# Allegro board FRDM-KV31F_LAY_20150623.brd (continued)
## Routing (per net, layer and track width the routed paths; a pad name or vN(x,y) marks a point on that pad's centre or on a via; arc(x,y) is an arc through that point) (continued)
PTA4: length 41.6
  TOP w0.152: U13.38 53.1,25.34 53.1,25.34 v1(53.36,25.09) ; SW2.1 72.8,47.79 70.68,45.67 C56.1 68.11,45.07 68.11,44.65 R1.2 67.74,43.76 67.72,43.74 67.72,41.84 66.08,40.2 v1(58.84,40.2)
  INT_1 w0.152: v1(53.36,25.09) 56.91,25.09 58.84,27.02 v1(58.84,40.2)
PTA5: length 34.6
  TOP w0.152: v1(43.11,28.09) 43.58,28.09 43.95,28.47 49.27,28.47 51.29,26.45 51.29,26.45 U13.39
  INT_1 w0.152: v1(43.11,28.09) 42.39,28.82 42.39,44.39 40.35,46.43 40.35,49.67 J2.4
PTA12: length 30.5
  TOP w0.152: U13.42 50.23,25.39 50.23,25.39 49.5,26.11 v1(48.28,26.11)
  INT_1 w0.152: v1(48.28,26.11) 46.55,27.83 46.55,42.52 49.53,45.5 49.53,49.55 J1.12
PTA13: length 38.4
  TOP w0.152: v1(48.88,25.58) 49.33,25.58 49.88,25.04 49.88,25.03 U13.43
  INT_1 w0.152: J1.3 59.65,49.61 52.64,49.61 52.06,49.03 52.06,47.14 46.91,41.99 46.91,28.26 48.88,26.3 v1(48.88,25.58)
PTA17: length 45.4
  TOP w0.152: v1(41.56,26.07) 46.02,26.07 U13.47
  INT_1 w0.152: J2.15 23.96,48.29 27.47,44.78 39.25,44.78 41.05,42.97 41.05,26.58 v1(41.56,26.07)
PTB0: length 32.6
  TOP w0.152: U13.53 48.11,17.92 47.5,17.31 v1(45.4,17.31) ; C522.1 45.13,43.14 R555.1 43.6,43.13 43.6,42.73 43.61,42.72 v1(43.61,42.38)
  INT_1 w0.152: v1(43.61,42.38) 43.09,41.86 43.09,39.66 44.68,38.07 44.68,18.03 v1(45.4,17.31)
PTB0_RC: length 4.9
  TOP w0.152: J2.1 41.73,47.07 43.59,45.21 R555.2
PTB1: length 59.9
  TOP w0.152: U13.54 47.38,16.48 R48.2 44,17.21 30.74,17.21 v1(30.41,17.54)
  INT_1 w0.152: v1(30.41,17.54) 30.41,22.84 28.11,25.15 23.15,25.15 22.59,25.71 22.59,39.12 22.58,39.13 22.58,39.51 22.59,39.51 22.59,39.61 22.59,39.61 22.59,49.64 22.15,50.08 22.15,50.09 J2.18
PTB2: length 63.5
  TOP w0.152: v1(29.25,17.03) 29.65,16.62 40.53,16.62 42.2,14.95 44.17,14.95 R41.2 45.09,15.88 47.48,15.88 48.82,17.21 48.82,17.21 U13.55
  INT_1 w0.152: J2.20 18.87,50.82 20.17,49.52 20.17,45.22 21.81,43.57 21.81,25.2 22.59,24.43 27.65,24.43 29.25,22.83 v1(29.25,17.03)
PTB3: length 43.5
  TOP w0.152: v1(36.1,41.73) 36.06,41.78 C516.1 36.05,43.26 34.63,43.26 R549.1 ; v1(40.82,15.54) 41.73,14.63 46.94,14.63 U13.56
  INT_1 w0.152: v1(36.1,41.73) 38.62,41.73 40.25,40.1 40.25,34.19 39.96,33.9 39.96,32.65 40.46,32.16 40.46,15.9 v1(40.82,15.54)
PTB3_RC: length 4.2
  TOP w0.152: J2.7 34.11,47.01 34.61,46.51 R549.2
PTB10: length 62.6
  TOP w0.152: U13.58 48.02,14.3 41.24,14.3 39.44,16.09 29.15,16.09 v1(28.79,16.46)
  INT_1 w0.152: v1(28.79,16.46) 28.79,22.67 27.4,24.06 22.41,24.06 21.44,25.03 21.44,43.2 18.87,45.77 J2.19
PTB11: length 16.7
  TOP w0.152: U13.59 50.11,15.68 v1(50.11,15.24)
  INT_1 w0.152: v1(50.11,15.24) 50.11,10.15 54.65,5.61 54.65,3.85 J4.6
PTB18: length 28.6
  TOP w0.152: U13.64 52,14.03 52,14.02 48.73,10.76 32.21,10.76 31.17,9.72 v1(31.17,8.35) 31.17,7.51 30.45,6.78 30.45,6.16 30.44,6.16 J3.3
PTB19: length 32.9
  TOP w0.152: J3.1 29.04,3.98 31.12,3.98 31.76,4.62 v1(31.76,9.03) 31.76,9.58 32.6,10.42 49.08,10.42 52.34,13.68 52.35,13.68 U13.65
PTB20: length 67.9
  TOP w0.152: U13.66 49.47,10.08 40.01,10.08 39.8,9.87 v1(33.65,9.87)
  INT_1 w0.152: v1(33.65,9.87) 29.83,13.7 29.83,22.81 27.84,24.8 22.85,24.8 22.21,25.44 22.21,43.94 21.41,44.74 J2.17
PTB21: length 14.4
  TOP w0.152: U13.67 52.79,12.7 v1(52.79,12.25)
  INT_1 w0.152: v1(52.79,12.25) 56.08,8.96 59.59,8.96 61,7.55 J4.9
PTB22: length 26.6
  TOP w0.152: R64.2 56.43,35.5 v1(59.33,32.61) ; v1(55,22.3) 55,14.2 U13.68
  INT_1 w0.152: v1(55,22.3) 59.33,26.63 v1(59.33,32.61)
PTC0: length 14.6
  TOP w0.152: U13.70 53,10.79 53,10.79 v1(52.69,10.48)
  INT_1 w0.152: v1(52.69,10.48) 53.6,9.57 53.6,8.57 54.44,7.73 56.52,7.73 57.17,7.08 57.17,3.87 J4.8
PTC1: length 14.9
  TOP w0.152: U13.71 54.47,11.56 52.67,9.75 46.15,9.75 v1(45.69,9.29)
  INT_1 w0.152: v1(45.69,9.29) 45.69,5.13 J3.15
PTC2: length 18.9
  TOP w0.152: U13.72 53.04,9.41 47.18,9.41 v1(46.8,9.03)
  INT_1 w0.152: J3.13 44.36,3.9 46.22,3.9 46.8,4.48 v1(46.8,9.03)
PTC3: length 59.7
  TOP w0.152: v1(56.62,12.87) 56.62,12.29 U13.73 ; v1(62.11,45.6) 50.87,45.6 49.58,46.89 49.58,49.52 J1.14
  INT_1 w0.152: v1(56.62,12.87) 60.55,12.87 64.45,16.77 64.45,18.83 66,20.38 66,36.27 64.33,37.95 64.33,39.98 62.46,41.85 62.46,45.25 v1(62.11,45.6)
PTC4: length 26.5
  TOP w0.152: U13.76 59.82,10.14 59.82,9.26 58.48,7.93 38.97,7.93 v1(38.64,7.6)
  INT_1 w0.152: J3.9 38.06,7.02 38.32,7.28 38.32,7.28 v1(38.64,7.6)
PTC5: length 24.8
  TOP w0.152: v1(41.22,7.44) 41.68,7.44 41.82,7.58 58.76,7.58 60.33,9.15 60.33,10.34 U13.77
  INT_1 w0.152: v1(41.22,7.44) 40.6,6.82 J3.11
PTC6: length 62.6
  TOP w0.152: v1(61.07,10.58) 60.79,10.58 60.51,10.86 60.51,10.86 U13.78 ; v1(63.55,44.46) 63.23,44.78 61.55,44.78 61.39,44.94 49.04,44.94 47.04,46.94 47.04,49.51 J1.16
  INT_1 w0.152: v1(61.07,10.58) 61.74,10.58 64.94,13.78 64.94,18.47 66.54,20.07 66.54,26.07 67.33,26.86 67.33,29.03 67.99,29.68 67.99,35.48 65.25,38.22 65.25,40.17 63.55,41.87 63.55,43.71 63.55,44 63.55,44 v1(63.55,44.46)
PTC7: length 73.5
  TOP w0.152: U13.79 59.44,12.64 59.43,12.64 59.34,12.73 59.18,12.73 57.84,11.4 57.84,9.33 56.77,8.26 42.9,8.26 v1(42.1,9.07)
  INT_1 w0.152: v1(42.1,9.07) 42.1,26.64 41.44,27.3 41.44,43.57 39.58,45.43 29.35,45.43 27.23,47.54 27.23,47.55 J2.13
PTC8: length 20.7
  TOP w0.152: J4.2 52.2,3.94 52.2,5.81 52.93,6.54 61.93,6.54 62.64,7.25 62.64,10.15 61.23,11.56 61.23,11.56 U13.80
PTC9: length 19.3
  TOP w0.152: J4.4 54.62,3.82 61.85,3.82 62.25,4.22 62.25,6.26 63.19,7.2 63.19,10.3 U13.81
PTC10: length 17.9
  TOP w0.152: J4.12 64.82,3.86 64.82,5.85 65.36,6.39 66.88,6.39 R50.2 68.32,7.83 68.32,8.77 67.65,9.44 64.76,9.44 61.94,12.26 U13.82
PTC11: length 23.9
  TOP w0.152: J4.10 62.29,1.28 64,1.28 65.23,2.52 65.23,5.49 65.76,6.02 68.08,6.02 R49.2 68.68,7.81 68.68,8.96 67.83,9.81 65.1,9.81 U13.83
PTC12: length 48.7
  TOP w0.152: U13.84 64.98,10.64 v1(65.82,10.64)
  INT_1 w0.152: J1.1 67.2,44.6 67.2,42.83 68.49,41.54 68.49,39.85 71.44,36.9 71.44,21.79 67.77,18.13 67.77,12.14 66.27,10.64 v1(65.82,10.64)
PTC13: length 59.7
  TOP w0.152: v1(65.44,11.29) 65.03,11.29 U13.85 ; v1(64.39,46.68) 64.07,47 60.27,47 59.92,46.66 55.1,46.66 54.6,47.15 54.6,49.57 J1.10
  INT_1 w0.152: v1(64.39,46.68) 66.79,44.27 66.79,42.67 68.1,41.36 68.1,39.65 71.04,36.71 71.04,21.96 67.27,18.19 67.27,12.3 66.27,11.29 v1(65.44,11.29)
PTC15: length 50.2
  TOP w0.152: v1(65.11,11.93) 63.97,13.06 63.97,13.75 63.69,14.04 63.69,14.04 U13.87
  INT_1 w0.152: v1(65.11,11.93) 66.19,11.93 66.87,12.61 66.87,18.35 70.64,22.12 70.64,36.51 67.72,39.43 67.72,41.13 66.44,42.4 66.44,43.91 63.14,47.21 59.5,47.21 58.43,48.28 J1.5
PTC16: length 47.3
  TOP w0.152: v1(66.28,14.55) 65.3,14.55 64.75,15.1 64.75,15.1 U13.90
  INT_1 w0.152: v1(66.28,14.55) 66.28,18.33 70.22,22.27 70.22,36.36 67.34,39.24 67.34,40.94 66.06,42.22 66.06,43.66 63.02,46.7 58.52,46.7 58.51,46.71 57.11,48.11 57.11,48.11 56.93,48.29 J1.7
PTC17: length 49.3
  TOP w0.152: v1(65.79,15.22) 65.35,15.22 65.11,15.46 65.11,15.46 U13.91 ; v1(65.57,43.31) 65.57,44.67 63.71,46.52 60.38,46.52 60.18,46.33 54.07,46.33 53.35,47.05 J1.9
  INT_1 w0.152: v1(65.79,15.22) 65.79,15.66 65.79,15.67 65.79,18.44 69.8,22.46 69.8,36.16 66.98,38.98 66.98,40.65 65.57,42.06 v1(65.57,43.31)
PTC18: length 27.9
  TOP w0.152: v1(47.64,32.01) 47.64,32.81 47.78,32.95 47.78,34.76 U8.9 ; v1(54.01,23.67) 57.61,23.67 U13.92
  INT_1 w0.152: v1(54.01,23.67) 53.3,23.67 47.64,29.33 v1(47.64,32.01)
PTD0: length 27.3
  TOP w0.152: v1(48.89,31.9) 48.89,32.36 48.78,32.47 U8.11 ; v1(54.5,24.14) 57.85,24.14 64.39,17.61 64.39,17.59 U13.93
  INT_1 w0.152: v1(48.89,31.9) 48.89,28.65 53.4,24.14 v1(54.5,24.14)
PTD1: length 9.3
  TOP w0.152: R69.1 73.12,13.37 v1(71.44,13.37) 69.32,13.37 66.19,16.51 66.18,16.51 U13.94
PTD2: length 55.8
  TOP w0.152: v1(74.86,30.88) 74.4,30.88 74.39,30.89 74.33,30.89 73.56,31.66 71.24,31.66 69.25,33.65 66.79,33.65 63.65,36.78 56.7,36.78 55.9,37.58 55.9,39.61 55.68,39.83 55.68,41.54 R9.2 54.31,42.92 48.82,42.92 48.26,42.36 v1(48.26,40.92) 48.26,37.33 U8.4 ; v1(72.03,17.5) 72.03,17.04 72.02,17.03 72.02,16.09 R56.2
  INT_1 w0.152: v1(74.86,30.88) 74.86,22.79 72.02,19.95 72.02,17.96 72.03,17.96 v1(72.03,17.5)
PTD3: length 61.5
  TOP w0.152: v1(74.38,31.59) 73.92,32.05 71.37,32.05 69.42,34.01 66.95,34.01 63.84,37.12 57.44,37.12 56.83,37.73 56.83,41.45 R15.2 56.2,42.09 55.01,43.28 48.49,43.28 46.39,41.19 46.39,39.87 43.91,37.39 v1(43.91,36.9) 44.29,36.52 47.49,36.52 U8.6 ; v1(71.17,17.86) 71.17,17.43 R57.1
  INT_1 w0.152: v1(71.17,17.86) 71.17,19.67 74.38,22.89 v1(74.38,31.59)
PTD4: length 44.1
  TOP w0.152: U13.97 68.13,16.68 v1(68.98,16.68) ; J3.7 36.73,6.32 41.84,6.32 42.41,6.9 61.15,6.9 v1(61.79,7.53)
  INT_1 w0.152: v1(68.98,16.68) 68.98,12.1 66.47,9.6 63.85,9.6 v1(61.79,7.53)
PTD5: length 45.5
  TOP w0.152: U13.98 66.87,18.65 67.6,17.92 67.6,17.92 68.04,17.47 68.05,17.47 v1(68.37,17.15) ; v1(61.48,8.29) 60.43,7.25 42.06,7.25 41.55,6.75 34.61,6.75 J3.5
  INT_1 w0.152: v1(61.48,8.29) 63.23,10.05 66.3,10.05 68.37,12.12 v1(68.37,17.15)
PTD6: length 61.4
  TOP w0.152: U13.99 66.5,19.73 63.08,19.73 59.57,23.24 59.57,23.24 v1(59.25,23.56)
  INT_1 w0.152: J2.6 36.65,50.86 38.09,52.3 42.33,52.3 44.23,50.4 44.23,42.25 43.45,41.47 43.45,39.86 45.03,38.29 45.03,26.73 51.03,20.73 56.42,20.73 v1(59.25,23.56)
PTD7: length 9.3
  TOP w0.152: R74.2 73.17,17.28 72.06,18.39 68.53,18.39 68.29,18.63 68.29,18.64 U13.100
PTE0: length 36.4
  TOP w0.152: v1(72.41,24.58) 71.76,23.94 R58.2
  INT_1 w0.152: v1(72.41,24.58) 72.41,32.4 72.41,32.4 72.41,33.06 72.41,33.06 72.41,37.1 69.16,40.35 69.16,42.07 68.16,43.07 68.16,44.92 65.02,48.06 65.02,51.16 64.13,52.05 62.22,52.05 61.72,51.55 61.7,51.55 J1.4
PTE1: length 30
  TOP w0.152: R59.1 71.35,25.38 71.35,25.37 71.62,25.37 v1(71.95,25.7)
  INT_1 w0.152: v1(71.95,25.7) 71.95,26.15 71.94,26.16 71.94,36.99 68.83,40.11 68.83,41.78 67.64,42.96 67.64,44.85 67.26,45.23 67.26,45.23 66.9,45.58 66.9,45.59 64.7,47.79 64.7,49.65 64.25,50.1 64.24,50.1 J1.2
PTE2: length 41.8
  TOP w0.152: v1(65.05,43.83) 65.05,44.29 65.05,44.63 63.54,46.14 60.62,46.14 60.44,45.97 51.7,45.97 50.81,46.86 J1.11 ; 66.87,22.54 68.08,23.75 68.29,23.75 v1(68.73,24.19)
  INT_1 w0.152: v1(68.73,24.19) 69.37,24.83 69.37,35.99 66.57,38.79 66.57,40.47 65.05,41.99 65.05,43.38 v1(65.05,43.83)
PTE3: length 43
  TOP w0.152: v1(64.57,43.35) 64.57,44.34 63.79,45.12 61.67,45.12 61.53,45.26 49.95,45.26 48.27,46.94 J1.13 ; U13.4 67.23,23.6 v1(67.99,24.37)
  INT_1 w0.152: v1(67.99,24.37) 68.92,25.29 68.92,35.79 66.14,38.56 66.14,40.34 64.57,41.92 v1(64.57,43.35)
PTE4: length 29.1
  TOP w0.152: v1(72.19,8.79) 72.19,8.33 72.28,8.24 C55.1 R75.2 72.28,5.31 72.8,4.79 SW3.1 ; R67.2 69.97,25.65 70.82,26.49 72.55,26.49 73.35,25.69 v1(73.35,24.64)
  INT_1 w0.152: v1(72.19,8.79) 72.19,9.32 70.51,11 70.51,19.65 73.35,22.49 v1(73.35,24.64)
PTE5: length 39.2
  TOP w0.152: v1(72.9,27.14) 72.43,27.14 72.43,27.14 69.1,27.14
  INT_1 w0.152: v1(72.9,27.14) 72.9,27.63 72.89,27.63 72.89,28.66 72.89,28.66 72.89,37.21 69.53,40.57 69.53,42.35 68.66,43.22 68.66,44.97 65.41,48.23 65.41,49.43 65.41,49.44 65.41,50.08 65.41,50.09 65.41,51.4 64.36,52.44 60.05,52.44 J1.6
PTE6: length 36.3
  TOP w0.152: U13.7 66.18,24.68 67.05,25.54 67.07,25.54 v1(67.39,25.86) ; v1(56.93,47.15) 56.93,47.61 57.15,47.83 57.15,49.57 J1.8
  INT_1 w0.152: v1(56.93,47.15) 57.92,46.17 62.78,46.17 64.08,44.87 64.08,41.88 65.74,40.22 65.74,38.34 68.43,35.65 68.43,29.58 67.82,28.98 67.82,26.29 v1(67.39,25.86)
PTE16: length 42
  TOP w0.152: J1.15 45.73,46.94 48.06,44.6 61.14,44.6 61.3,44.44 62.61,44.44 v1(63,44.06) ; v1(66.61,27.23) 66.29,26.91 U13.10
  INT_1 w0.152: v1(63,44.06) 63,43.6 63,43.6 63,41.87 64.8,40.06 64.8,38.06 67.52,35.34 67.52,29.79 66.94,29.21 66.94,27.56 v1(66.61,27.23)
PTE17: length 60.2
  TOP w0.152: U13.11 62.19,23.51 61.39,23.51 60.54,24.36 v1(60.06,24.36) ; J2.12 30.36,49.5 30.36,43.44 32.04,41.76 34.02,41.76 35.86,39.92 v1(44.19,39.92)
  INT_1 w0.152: v1(44.19,39.92) 45.42,38.68 45.42,26.95 51.29,21.09 55.9,21.09 59.17,24.36 v1(60.06,24.36)
PTE18: length 54.1
  TOP w0.152: v1(59.56,24.87) 60.76,24.87 61.38,24.25 62.21,24.25 62.96,24.99 62.96,24.99 U13.12 ; v1(43.93,40.92) 38.56,40.92 37.08,42.4 37.08,45.87 35.36,47.6 35.36,49.58 J2.8
  INT_1 w0.152: v1(59.56,24.87) 59.06,24.87 55.65,21.46 51.56,21.46 45.8,27.22 45.8,39.05 44.25,40.59 44.25,40.6 v1(43.93,40.92)
PTE19: length 56.3
  TOP w0.152: v1(58.95,25.38) 60.89,25.38 61.56,24.71 61.97,24.71 U13.13 ; v1(45.21,40.39) 36.52,40.39 33.94,42.97 33.94,46.39 32.88,47.45 32.88,49.51 J2.10
  INT_1 w0.152: v1(45.21,40.39) 46.17,39.44 46.17,27.5 51.83,21.84 55.41,21.84 v1(58.95,25.38)
PTE24: length 34.2
  TOP w0.152: U13.31 53.31,30.08 53.25,30.08 53.25,30.09 43.39,30.09 v1(43.13,30.34)
  INT_1 w0.152: v1(43.13,30.34) 42.75,30.72 42.75,42.34 43.62,43.21 43.62,48.94 J2.2
PTE25: length 45
  TOP w0.152: U13.32 54.51,28.19 v1(55.52,27.19) ; v1(75.37,30.24) 74.28,30.24 73.27,31.25 71.11,31.25 69.08,33.29 66.57,33.29 63.41,36.45 58.41,36.45 v1(57.74,35.78) ; R73.2 73.34,18.35 73.07,18.35 v1(72.58,18.84)
  INT_1 w0.152: v1(57.74,35.78) 57.29,35.32 57.29,28.96 v1(55.52,27.19) ; v1(75.37,30.24) 75.37,22.78 72.58,19.98 v1(72.58,18.84)
RST_TGTMCU_B: length 149.7
  TOP w0.152: v1(24.92,39.74) 25.2,39.46 R10.2 R11.2 U3.7 ; TP33.1 67.92,40.45 67.06,39.58 58.04,39.58 57.41,40.21 57.41,42.51 56.32,43.6 48.27,43.6 45.94,41.27 45.94,40.11 45.12,39.29 35.9,39.29 33.81,41.38 31.85,41.38 29.38,43.85 25.25,43.85 v1(24.92,43.53) 24.42,43.53 24.35,43.46 11.84,43.46 10.25,41.87 D1.C 6.76,42.44 6.75,42.45 6.75,42.64 6.5,42.89 4.82,42.89 4.42,43.29 J25.3 ; v1(30.95,18.24) 31.37,17.81 38.64,17.81 38.64,17.82 v1(39.25,17.82) 47.3,17.82 47.76,18.27 U13.52
  TOP w0.203: J9.10 73.15,38.1 70.8,40.45 70.22,40.45 70.22,40.45 TP33.1
  INT_1 w0.152: J3.6 34.26,3.86 34.26,10.62 30.95,13.93 v1(30.95,18.24) 30.95,22.9 28.34,25.5 27.09,25.5 26.49,26.1 26.49,37.49 24.92,39.06 v1(24.92,39.74) 24.92,43.08 24.92,43.08 v1(24.92,43.53)
SDA_EXTAL: length 6.3
  TOP w0.152: U5.17 16.88,38.73 17.36,38.73 17.55,38.55 17.55,37.13 C9.1 18.76,36.43 19.07,36.74 Y1.3
SDA_JTAG_TCLK: length 11.7
  TOP w0.152: J10.4 13.91,30.14 TP26.1 ; v1(16.29,34.67) 15.98,34.98 15.98,34.99 15.87,35.09 15.01,35.95
  INT_1 w0.152: v1(16.29,34.67) 16.29,31.39 13.91,29.02 J10.4
SDA_JTAG_TDI: length 12
  TOP w0.152: J10.8 16.45,29.38 16.7,29.63 TP28.1 ; U5.13 17.14,34.53 17.14,34.53 v1(17.45,34.22)
  INT_1 w0.152: J10.8 16.45,29.8 17.45,30.8 v1(17.45,34.22)
SDA_JTAG_TDO: length 12.2
  TOP w0.152: TP27.1 15.33,29.59 15.18,29.43 J10.6 ; U5.14 16.63,35.75 16.63,35.74 v1(16.94,35.43)
  INT_1 w0.152: J10.6 15.18,29.58 16.94,31.34 v1(16.94,35.43)
SDA_JTAG_TMS: length 14.2
  TOP w0.152: U5.15 16.07,36.99 v1(16.72,36.35) R21.2 18.25,33.85 TP25.1
  INT_1 w0.152: J10.2 13.13,28.45 13.13,28.92 15.78,31.57 15.78,35.42 v1(16.72,36.35)
SDA_LED: length 9.8
  TOP w0.152: U5.29 10.69,40.28 3.3,40.28 2.98,39.95 D2.C
SDA_LED_R: length 5.7
  TOP w0.152: v1(1.99,37.77) 2.96,37.77 D2.A ; R17.2 2.93,34.31 2.18,34.31 1.91,34.58 v1(1.88,34.58)
  INT_1 w0.152: v1(1.99,37.77) 1.56,37.34 1.56,34.9 v1(1.88,34.58)
SDA_RST: length 20.7
  TOP w0.152: J10.10 17.72,28.77 TP29.1 ; U5.19 16.48,39.75 16.54,39.75 v1(16.85,40.06) ; TP5.1 18.77,32.38 v1(18.77,32.97) 19.21,32.97 19.24,32.94 R6.1 R5.2
  INT_1 w0.152: v1(16.85,40.06) 17.66,39.25 17.66,39.25 17.66,35.67 18.77,34.56 v1(18.77,32.97) 18.3,32.5 18.3,30.77 17.72,30.19 J10.10
SDA_RST_LED: length 1.4
  TOP w0.152: D1.A 4.6,41.87 4.59,41.85 R2.2
SDA_RST_TGTMCU_B: length 6.2
  TOP w0.152: 15.01,39.7 15.41,40.1 15.41,40.1 15.53,40.21 15.53,40.21 v1(15.85,40.54)
  INT_1 w0.152: v1(15.85,40.54) 15.85,41.38 13.58,43.65 13.58,44.6 J5.2
SDA_RST_TGTMCU_J_B: length 34
  TOP w0.152: v1(24,43.94) 22.46,43.94 21.83,44.57 21.83,44.57 21.78,44.62 J5.1 16.14,45.59 15.89,45.84 10.71,45.84 J25.1 ; U3.2 29.37,38.56 29.51,38.42 29.51,37.23 R14.2 28.23,35.96 v1(25.83,35.96) 25.37,35.96 25.37,35.96 25.21,35.96 24.94,36.23 24.94,37.68 R10.1
  INT_1 w0.152: v1(25.83,35.96) 25.83,37.46 24.32,38.97 24.32,43.62 v1(24,43.94)
SDA_RX_EN: length 3.4
  TOP w0.152: U7.5 34.16,36.04 34.18,36.06 R16.1 34.7,35.64 34.84,35.5 v1(34.84,35.04) 34.84,34.93 34.81,34.9 34.81,34.87 R23.2
SDA_SPI0_CS: length 12.2
  TOP w0.152: R3.2 24.08,40.81 TP1.1 23.53,41.36 15.26,41.36 14.7,40.8 U5.23
SDA_SPI0_RST_B: length 17.7
  TOP w0.152: U5.22 15.05,40.45 15.63,41.02 22.87,41.02 v1(23.12,40.77) ; TP6.1 23.6,36.65 23.59,36.64 23.59,36.34 23.74,36.19 23.74,36.15 v1(23.75,36.14) 24.2,36.14 24.22,36.13 24.3,36.13 25.01,35.43 R18.2
  INT_1 w0.152: v1(23.12,40.77) 23.63,40.26 23.63,36.72 23.75,36.6 v1(23.75,36.14)
SDA_SPI0_SCK: length 24.3
  TOP w0.152: U2.3 33.64,40.61 33.36,40.89 31.77,40.89 30.28,42.37 12.69,42.37 12.28,41.97 12.28,40.8 U5.26
SDA_SPI0_SIN: length 34.6
  TOP w0.152: v1(27.16,43.2) 26.47,43.2 26.34,43.06 12.17,43.06 11.43,42.32 11.43,40.24 U5.28 ; U10.5 30.09,29.08 29.5,29.67 29.11,29.67 v1(28.8,29.98)
  INT_1 w0.152: v1(27.16,43.2) 27.92,42.44 27.92,38.71 28.8,37.83 v1(28.8,29.98)
SDA_SPI0_SOUT: length 31.1
  TOP w0.152: U12.3 30.08,32.4 30.08,32.41 v1(30.08,32.86) ; U5.27 11.8,40.58 11.8,42.11 12.41,42.72 27.65,42.72 27.83,42.9 v1(28.3,42.9)
  INT_1 w0.152: v1(30.08,32.86) 30.08,33.32 30.07,33.33 30.07,33.47 30.07,33.47 30.07,34.88 29.84,35.11 29.84,41.34 29.82,41.36 29.82,41.38 28.62,42.58 28.62,42.58 v1(28.3,42.9)
SDA_SWD_EN: length 2.5
  TOP w0.152: U9.6 27.49,35.42 R18.1 R19.1
SDA_SWD_EN_B: length 10.3
  TOP w0.152: R25.2 24.76,34.81 24.76,35.06 24.23,35.6 23.61,35.6 23.46,35.44 TP52.1 18.14,35.44 17.24,36.34 17.24,36.56 U5.16
SDA_SWD_EN_B_R: length 2.4
  TOP w0.152: U9.1 27.14,33.38 27.11,33.4 R26.2 25.16,33.4 R25.1
SDA_SWD_EN_R: length 6.7
  TOP w0.152: R19.2 30.42,35.43 31.35,36.36 R13.1 31.35,37.9 31.37,37.91 R12.2 31.37,39.24 31.89,39.76 U2.5
SDA_SWD_OE: length 16.5
  TOP w0.152: v1(24.66,32.11) 24.88,31.88 28.45,31.88 29.16,32.6 29.16,33.54 28.75,33.95 28.67,33.95 U9.4 28.49,34.31 28.76,34.58 31.21,34.58 R33.1 ; R3.1 24.08,37.43 v1(24.48,37.02)
  INT_1 w0.152: v1(24.66,32.11) 24.48,32.28 v1(24.48,37.02)
SDA_SWD_OE_B: length 14.5
  TOP w0.152: v1(23.17,39.32) 23.17,39.86 22.81,40.22 TP50.1 22.11,40.61 16.63,40.61 15.75,39.73 U5.20 ; R28.2 24.15,34.74 v1(23.83,35.07)
  INT_1 w0.152: v1(23.17,39.32) 23.17,35.72 v1(23.83,35.07)
SDA_SWD_OE_B_R: length 6.9
  TOP w0.152: R27.1 23.64,33.35 23.65,33.36 R28.1 24.95,32.56 v1(25.64,32.56) 26.02,32.18 28.26,32.18 28.49,32.42 U9.3
SDA_SWD_OE_R: length 7.1
  TOP w0.152: R39.1 32.42,30.79 31.91,30.28 30.8,30.28 30.58,30.5 U12.5 ; R39.1 32.94,31.31 31.68,32.57 R33.2 ; R39.1 32.94,29.63 R37.2
SDA_USB_CONN_DN: length 17
  TOP w0.152: R22.1 9.51,34.31 8.86,33.66 8.86,33.39 v1(9.12,33.14) ; J6.2 5.09,26.52 5.27,26.34 6.77,26.34 U4.1 8.07,26.37 10.1,26.37 v1(10.31,26.59)
  INT_1 w0.152: v1(10.31,26.59) 9.99,26.27 9.6,26.27 8.85,27.02 8.85,32.88 v1(9.12,33.14)
SDA_USB_CONN_DP: length 17.9
  TOP w0.152: R20.1 9.25,34.57 8.55,33.86 8.55,33.43 v1(8.26,33.14) ; J6.3 4.16,25.87 5.15,25.87 5.31,26.03 6.83,26.03 7.45,25.41 U6.1 8.15,26.06 9.98,26.06 v1(10.31,25.73)
  INT_1 w0.152: v1(10.31,25.73) 10.11,25.94 9.47,25.94 8.52,26.88 8.52,27.15 8.52,32.88 v1(8.26,33.14)
SDA_USB_DN: length 1.7
  TOP w0.152: U5.4 11.47,36.15 11.35,36.15 10.68,35.49 R22.2
SDA_USB_DP: length 1.8
  TOP w0.152: U5.3 11.11,36.51 11.11,36.36 10.48,35.73 R20.2
SDA_USB_P5V_SENSE: length 6
  TOP w0.152: R8.2 R7.1 7.4,39.36 7.4,39.36 v1(7.78,39.74) 7.78,39.74 10.52,39.74 U5.30
SDA_USBSHIELD: length 20.9
  TOP w0.152: J6.S1 5.37,28.1 ; 2.62,30.05 J6.S3 1.48,31.55
  TOP w0.381: 3.87,30.85 L1.1 5.33,28.96 4.48,28.11 J6.S1 4.31,28.1 3.68,28.73
  BOTTOM w0.127: J6.S2 4.48,24.37 ; J6.S2 3.59,23.65 ; J6.S2 4.48,22.92 ; J6.S2 5.37,23.65 ; J6.S3 2.62,30.05 ; J6.S3 1.48,29.31 ; J6.S3 1.48,30.78 ; 3.59,28.1 J6.S1 ; J6.S1 4.48,28.82 ; J6.S1 4.48,27.37 ; J6.S1 5.37,28.1 ; 1.48,20.96 J6.S4 ; J6.S4 1.48,22.43 ; J6.S4 2.62,21.7
SDA_VOUT33: length 12.3
  TOP w0.203: v1(11.38,35.34) 11.56,35.52 11.56,35.54 U5.5
  TOP w0.508: C11.1 6.99,34.36 v2(5.84,34.36) 4.72,34.36 R36.2 4.52,34.28 3.93,33.7 3.92,33.7 TP15.1
  INT_1 w0.381: v2(5.84,34.36) 5.84,35.05 6.69,35.9 9.55,35.9 10.1,35.35 11.36,35.35 v1(11.38,35.34)
SDA_XTAL: length 5
  TOP w0.152: 16.07,38.64 16.47,39.03 16.48,39.03 16.88,39.44 C6.1 18.88,39.44 19.18,39.14 19.36,39.14 19.37,39.13 Y1.1
SW1_RST_B: length 6.5
  TOP w0.152: v1(7.4,47.38) 7.42,47.38 7.43,47.39 C2.1 8.28,48.38 8.02,48.64 SW1.2
  INT_1 w0.152: v1(7.4,47.38) 6.96,46.94 J25.2
SWD_CLK_KV3X: length 21.1
  TOP w0.152: J11.1 36.72,34.9 36.72,33.28 36.96,33.04 39.38,33.04 42.71,29.7 50.81,29.7 52.3,28.21 53.06,28.21 U13.34
SWD_CLK_TGTMCU: length 47.1
  TOP w0.152: TP31.1 70.16,36.61 66.03,36.61 64.31,38.34 v1(57.38,38.34) ; J8.2 39.37,31.02 40.89,31.02 41.75,30.16 41.75,29.55 TP42.1 42.06,29.24 v1(50.63,29.24)
  TOP w0.203: J9.4 73.73,34.29 71.4,36.62 TP31.1
  INT_1 w0.152: 39.26,34.87 39.25,34.86 J11.2 39.32,34.84 39.32,31.08 J8.2 ; v1(50.63,29.24) 56.13,34.74 56.13,37.09 v1(57.38,38.34)
SWD_CLK_TGTMCU_BUF: length 12.1
  TOP w0.152: U2.4 v1(31.99,40.26)
  INT_1 w0.152: J8.1 36.78,31.08 36.78,32.39 33.63,35.53 33.63,35.53 33.46,35.7 33.46,38.78 v1(31.99,40.26)
SWD_DIO_TGTMCU: length 46
  TOP w0.152: v1(57.73,37.65) 63.97,37.65 66.06,35.56 TP30.1 ; J12.2 40.33,27.48 40.43,27.58 TP41.1 43,28.84 50.31,28.84 50.71,28.44 50.72,28.44 v1(51.04,28.12) 52,27.16 52,27.15 U13.37
  TOP w0.203: TP30.1 73.77,33.02 J9.2
  INT_1 w0.152: v1(57.73,37.65) 56.71,36.63 56.71,33.79 v1(51.04,28.12)
SWD_DIO_TGTMCU_BUF: length 15.3
  TOP w0.152: U12.4 30.08,30.45 30.53,30.01 32.2,30.01 32.4,29.8 32.4,29.41 32.74,29.07 35.24,29.07 J12.1 35.92,26.57 33.97,26.57 31.97,28.58 U10.2
TC_EXTAL_TP: length 4
  TOP w0.152: TP9.1 16.15,33.4 14.7,34.85 14.7,34.85 U5.10
TC_SDA_USB_ID_TP: length 4.3
  TOP w0.203: J6.4 4.16,25.22 5.28,25.22 TP7.1
TC_XTAL_TP: length 2.3
  TOP w0.152: TP10.1 14.86,33.98 14.33,34.5 14.33,34.51 U5.9
THER_A: length 13.4
  TOP w0.152: R47.2 68.91,28.96 71.28,28.96 C21.1 72.17,28.59 72.5,28.92 73.33,28.92 74.27,27.98 77.28,27.98 77.51,27.75 77.51,27.53 76.95,26.97 RT1.1 76.95,25.19 R45.2
THER_B: length 12.9
  TOP w0.152: R44.1 78.48,25.17 RT1.2 78.48,26.97 77.84,27.61 77.84,27.92 77.51,28.26 74.47,28.26 73.53,29.2 72.05,29.2 C21.2 71.28,29.24 69.76,29.24 R46.2
TP_2102_A: length 2.1
  TOP w0.152: U3.3 29.27,38.96 30.06,39.74 30.06,39.79 30.07,39.8 TP3.1
TP_2102_B: length 2.4
  TOP w0.152: U3.6 26.76,39.36 TP2.1
TRACE_SWO: length 4.4
  TOP w0.203: R80.1 72.65,37.89 72.99,37.56 72.99,36.07 73.49,35.56 J9.6
UART0_RX_TGTMCU: length 31.4
  TOP w0.152: v1(32.88,32.36) 32.88,33.07 R24.2 ; v1(32.88,15.02) 33.15,14.75 TP39.1 39.17,13.17 R54.2
  INT_1 w0.152: v1(32.88,15.02) 32.88,15.99 32.88,15.99 v1(32.88,32.36)
UART0_TX_TGTMCU: length 26.7
  TOP w0.152: v1(32.25,14.75) 32.51,14.49 32.7,14.3 32.82,14.18 32.83,14.18 33.06,13.95 33.07,13.95 TP40.1 37.94,13.95 37.99,13.95 39.11,12.83 43.78,12.83 45,11.61 45.86,11.61 R55.1 ; R38.2 v1(32.08,24.78)
  INT_1 w0.152: v1(32.25,14.75) 32.25,24.15 32.08,24.32 v1(32.08,24.78)
UART1_RX_PKYK: length 3.8
  TOP w0.152: U13.2 67.94,22.9 67.94,22.9 68.39,23.35 68.73,23.35 R59.2
UART1_RX_TGTMCU_BUF: length 1.7
  TOP w0.152: U7.4 33.66,34.99 R24.1
UART1_RX_TGTMCU_R: length 28.2
  TOP w0.152: v1(30.54,41.34) 30.22,41.66 30.21,41.66 29.84,42.03 12.9,42.03 12.65,41.79 12.65,41.14 U5.25 ; U7.3 31.94,35.54 TP49.1 31.47,35.06 30.87,35.06 v1(30.79,35.14)
  INT_1 w0.152: v1(30.54,41.34) 30.92,40.95 30.92,35.73 30.79,35.6 v1(30.79,35.14)
UART1_TX_PKYK: length 5.2
  TOP w0.152: R58.1 70.77,24.65 69.13,23.02 68.77,23.02 68.29,22.54 68.29,22.54 U13.1
UART1_TX_TGTMCU_BUF: length 1.6
  TOP w0.152: U10.1 31.38,27.48 R38.1
UART1_TX_TGTMCU_R: length 30.2
  TOP w0.152: U10.6 30.18,28.58 29.7,28.58 29.4,28.87 v1(29.38,28.87) 29.06,28.54 TP48.1 ; v1(29.38,41.15) 28.84,41.69 14.88,41.69 14.33,41.15 14.33,41.14 U5.24
  INT_1 w0.152: v1(29.38,41.15) v1(29.38,28.87)
V_TGTMCU: length 39.8
  TOP w0.203: U3.8 27.19,38.56 27.03,38.4 v1(27.03,37.93) ; U2.6 32.88,38.87 32.88,38.87 C7.1 33.66,37.26 U7.6 ; C23.1 30.98,27.3 30.78,27.5 U10.8 ; U12.6 31.63,30.91 31.68,30.95 v1(31.9,30.95)
  TOP w0.381: C7.1 32.13,38.04 v1(32.12,38.03) ; SH1.1 v1(30.34,24.53) 30.32,24.55 30.32,26.13 30.61,26.42 30.61,26.43 30.67,26.49 30.73,26.52 30.77,26.54 C23.1 ; v1(27.03,37.93) 26.3,37.93 R11.1 ; v1(26.38,44.49) 25.7,45.17 TP44.1 18.12,45.17 16.9,46.39 3.55,46.39 2.81,45.65 v1(2.81,42.76) 2.81,41.87 R2.1
VREFH: length 20.8
  TOP w0.203: U13.23 60.54,30.35 60.55,30.35 61.88,31.69 62.12,31.69 62.9,32.47 62.9,33.12 C34.1
  TOP w0.381: v1(62.8,34.12) 62.06,34.12 C33.1 C34.1
  TOP w0.508: R66.2 61.97,42.09 R68.2 64.09,41.24 R53.1 ; R66.2 61.95,41.15 v1(61.93,41.13) ; R66.2 61.93,42.09 60.5,42.09 D7.C
  INT_1 w0.381: v1(62.8,34.12) 62.8,40.26 v1(61.93,41.13)
VREFL: length 7
  TOP w0.152: 60.82,33.77 60.82,33.76 60.85,33.73 ; 61.6,32.09 61.59,32.11
  TOP w0.203: U13.24 60.19,30.71 60.19,30.71 61.59,32.11 ; 61.6,32.09 61.71,32.09 62.1,32.48 C33.2 ; C33.2 61.26,33.29 60.99,33.01 v1(60.99,32.45) ; C33.2 60.85,33.73 ; R62.2 60.82,33.77
VTRG_EN: length 5.7
  TOP w0.152: R34.2 26.55,29.64 26.54,29.65 U11.3 24.78,30.43 24.89,30.55 R30.1 24.39,31.34 24.37,31.32 R29.2
VTRG_FAULT_B: length 22.1
  TOP w0.152: v1(14.23,31.27) 14.69,30.81 19.41,30.81 19.93,30.28 R35.2 20.67,28.78 21.55,29.65 U11.4 ; U5.32 10.17,38.67 v1(9.17,38.67)
  INT_1 w0.152: v1(14.23,31.27) 13.4,32.1 13.4,34.86 10.93,37.33 9.75,37.33 9.17,37.9 v1(9.17,38.67)
XTAL0: length 10.1
  TOP w0.152: C38.2 39.3,20.07 41.2,20.07 X501.3 43.08,20.02 R52.2 44.66,20.34 TP36.1 45.33,20.42 47.12,18.63 47.4,18.63 U13.51
N20314503: length 7
  TOP w0.152: U8.16 50.07,36.52 52.52,36.52 v1(52.52,36.52) 54.48,36.52 54.48,36.52 R64.1 55.33,37.69 55.31,37.71 R42.1
N20919516: length 7.2
  TOP w0.152: U13.62 51.31,14.75 51.3,14.75 48.99,12.44 47.73,12.44 47,13.17 R54.1
N20919519: length 8.8
  TOP w0.152: U13.63 49.26,12 47.55,12 47.2,12.35 46.89,12.65 45.88,12.65 R55.2
N20920203: length 3.9
  TOP w0.152: R65.2 68,26.04 68,25.79 U13.6
N20920206: length 5.1
  TOP w0.152: R67.1 69.11,26.37 68.39,25.65 68.39,25.47 66.89,23.97 U13.5
N20923344: length 4.8
  TOP w0.152: TP43.1 74.36,20.08 R88.2 75.07,18.83 75.07,18.11 75.53,17.65 75.76,17.65 75.8,17.62 D4.2
N21097088: length 2.8
  TOP w0.152: U13.33 53.23,28.75 52.77,28.75 52.06,29.45 TP18.1

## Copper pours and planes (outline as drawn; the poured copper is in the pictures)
GND on TOP: 79.45,30.15 76.42,30.15 76.09,29.82 73.45,29.82 72.65,30.61 70.87,30.61 68.78,32.71 64.99,32.71 64.6,32.31 64.6,31.81 64.78,31.63 65.46,31.63 65.98,32.16 68.67,32.16 69.9,30.92 69.9,29.89 70.03,29.76 72.23,29.76 72.59,29.41 73.93,29.41 74.81,28.52 78.2,28.52 79.21,27.51 79.21,27.49 79.3,27.4 79.32,27.4 79.32,23.24 78.92,22.85 76.06,22.85 75.43,23.48 75.43,24.23 76.04,24.85 76.04,27.27 75.62,27.69 73.84,27.69 73,28.52 73,28.64 72.48,28.64 72.06,28.22 71.18,28.22 70.72,28.68 68.76,28.68 68.38,29.06 68.05,29.06 67.46,29.65 67.46,30.99 67.24,31.21 66.68,31.21 66.39,30.92 66.39,29.38 68.09,27.69 72.89,27.69 73.93,26.65 73.93,23.11 75.07,21.97 79.85,21.97 80.42,22.54 80.42,29.6 79.85,30.18 79.47,30.18
GND on TOP: 9.8,33.72 9.64,33.89 9.61,33.89 8.93,34.57 8.89,34.61 8.89,35.33 8.79,35.44 8.01,35.44 7.78,35.2 7.78,34.29 7.32,33.88 7.34,32.79 7.67,32.46 7.67,30.06 7.67,30.06 8.27,29.46 8.27,26.75 8.45,26.57 9.26,26.57 9.83,27.13 10.62,27.13 10.95,26.8 10.95,25.33 10.77,25.15 9.71,25.15 9.24,24.67 9.24,24.65 6.76,24.65 6.76,24.26 7.18,23.85 11.05,23.85 11.56,24.35 11.56,31.98 9.82,33.72
GND on TOP: 46.2,22.74 44.52,22.74 44.04,23.23 37.34,23.23 36.97,22.87 36.97,19.56 37.34,19.18 37.34,19.18 44.47,19.18 44.96,19.67 45.55,19.67 46.33,18.89 46.36,18.89 46.36,18.37 46.18,18.2 36.77,18.2 35.81,19.16 35.81,23.41 36.46,24.06 45.81,24.06 46.38,23.49 46.38,22.92
GND on TOP: 18.13,40.28 22.14,40.28 22.79,39.62 22.79,36.21 22.28,35.69 19.17,35.69 18.93,35.94 18.93,36.17 19.1,36.33 21.77,36.33 21.98,36.55 21.98,37.11 21.73,37.37 19.01,37.37 18.71,37.07 18.11,37.07 17.98,37.2 17.98,38.73 18.08,38.84 18.84,38.84 19.2,38.48 21.71,38.48 21.95,38.71 21.95,39.53 21.61,39.87 18.22,39.87 18.13,39.95
GND on TOP: 66.41,21.3 66.41,20.01 58.04,11.63 57.45,11.63 49.33,19.75 49.33,20.85 57.5,29.02 58.69,29.02 ; 1 cut-out
GND on TOP: 31.42,14.17 31.42,11.54 31.84,11.12 48.19,11.12 48.25,11.18 48.23,11.2 48.23,13.68 47.79,14.12 40.92,14.12 39.09,15.95 31.55,15.95 31.13,15.53 31.13,14.55 31.14,14.46 ; 2 cut-outs
GND on BOTTOM: 5.6,0.36 25.47,0.36 25.69,0.58 25.69,10.53 25.21,11.01 20.12,11.01 19.42,11.72 19.42,20.9 17.47,22.85 8.59,22.85 4.94,19.21 2.81,19.21 0.52,16.91 0.52,5.43
GND on BOTTOM: 4.44,52.67 41.53,52.67 42.26,51.95 42.26,44.51 41.8,44.05 40.81,44.05 40.06,43.3 1.53,43.3 0.92,43.9 0.92,49.16
GND on GND: 8.08,52.99 5.4,52.99 0.54,48.13 0.59,48.08 0.59,34.47 5.04,30.02 5.04,21.95 0.63,17.54 0.63,4.97 5.11,0.49 75.64,0.49 80.76,5.61 80.76,48.02 75.75,53.03 8.12,53.03
GND on INT_1: 0.85,18.88 5.34,23.37 5.34,29.17 1.16,33.36 1.16,48.8 4.94,52.58 18.15,52.58 18.36,52.36 18.36,50.95 24.61,44.71 24.61,26.54 27.15,23.99 31.21,23.99 31.21,28.25 31.25,28.29 31.48,28.29 33.76,30.58 33.76,43.08 31.39,45.45 24.26,45.45 20.65,49.06 20.65,50.82 22.59,52.76 74.51,52.76 80.49,46.77 80.49,6.29 74.68,0.49 6.84,0.49 0.85,6.47 ; 40 cut-outs
P3V3 on TOP: 27.3,17.6 25.17,17.6 24.88,17.89 24.88,19.75 24.36,20.27 22.26,20.27 22.18,20.19 22.18,14.57 22.3,14.45 25.77,14.45 31.19,19.87 31.19,19.87 31.35,20.02 31.35,22.94 30.87,23.42 28.68,23.42 28.12,23.99 28.12,24.87 26.62,24.87 26.1,24.35 26.1,21.6 26.5,21.2 29.93,21.2 29.93,20.23 29.73,20.03 29.72,20.03
P3V3 on BOTTOM: 21.54,20.48 20.58,21.44 18.94,21.44 18.94,23.66 19.92,24.63 37.07,24.63 38.4,25.96 38.4,42.08 39.17,42.84 41.96,42.84 42.78,43.67 42.78,51.61 43.71,52.53 76.28,52.53 80.61,48.2 80.61,5.21 76.18,0.78 26.8,0.78 26.35,1.23 26.35,8.47 26.53,8.64 24.12,11.04 22.59,11.04 21.54,12.1 ; 2 cut-outs
P3V3_KV31 on BOTTOM: 40.34,20.37 43.28,23.31 43.32,23.31 43.32,27.53 47.91,32.12 59.38,32.12 60.2,32.95 60.2,43.26 61.03,44.08 64.5,44.08 65.57,43.01 65.57,42.51 69.47,38.61 69.47,38.29 73.62,34.14 73.64,34.14 73.76,34.01 76.15,34.01 76.64,33.52 76.64,31.36 73.63,28.35 73.63,21.28 60.83,8.48 53.1,8.48 44.3,17.28 41.57,17.28 40,15.71 32.17,15.71 31.57,15.11 25.64,15.11 25.44,15.32 25.44,19.52 26.29,20.37 ; 1 cut-out
P3V3_SDA on TOP: 21.83,22.09 21.83,23.88 22.42,24.47 24.05,24.47 26.02,26.44 27.28,26.44 27.91,27.06 27.91,27.11 29.96,27.11 30.05,27.02 30.05,26.51 29.86,26.31 28.56,26.31 28.06,25.81 28.06,25.75 27.76,25.45 26.57,25.45 25.45,24.33 25.45,21.18 25.06,20.79 22.09,20.79 21.85,21.04 21.85,22.07
P3V3_SDA on BOTTOM: 0.93,42.28 0.93,36.49 1.57,35.84 5.14,35.84 5.43,36.13 5.43,36.85 5.05,37.22 5.05,38.44 5.38,38.77 6.29,38.77 9.66,35.39 11.21,35.39 11.9,34.7 11.9,32.22 11.83,32.15 11.83,31.06 11.51,30.74 11.51,25.7 11.61,25.6 13.24,25.6 14.91,27.27 19.75,27.27 20.19,27.71 20.19,32.96 20.15,33 20.64,33.49 27.71,33.49 28.66,32.53 28.66,26.07 28.84,25.89 36.47,25.89 36.9,26.32 36.9,40.74 35.26,42.38 1.03,42.38
P3V3_VREG on TOP: 12.93,21.24 11.6,19.91 11.6,17.74 10.61,16.76 8.92,16.76 8.89,16.74 8.89,15.73 8.94,15.68 10.64,15.68 11.57,14.75 11.57,13.83 12.16,13.24 20.07,13.24 20.07,13.25 20.77,13.94 20.77,17.21 21.44,17.88 21.44,20.21 21.13,20.52 18.7,20.52 18.37,20.84 17.98,21.24
P5V_OPT_VR on TOP: 5.67,2.47 5.05,1.84 3.78,1.84 3.23,2.4 3.23,6.7 3.68,7.15 5.53,7.15 5.61,7.06 5.67,7
P5V_SDA on BOTTOM: 23.63,33.02 20.77,33.02 20.38,32.64 20.38,27.12 20.05,26.78 16.76,26.78 15.29,25.32 11.54,25.32 10.82,26.04 10.82,30.91 11.54,31.63 11.54,34.98 11.39,35.14 9.48,35.14 6.57,38.05 6.57,38.13 5.75,38.13 5.54,37.92 5.54,35.94 5.13,35.52 0.72,35.52 0.5,35.3 0.5,33.06 0.67,32.89 5.54,32.89 6.42,32.02 6.42,24.24 7.43,23.23 7.43,23.22 17.48,23.22 19.62,25.37 27.81,25.37 28.32,25.88 28.32,32.22 27.47,33.07 23.68,33.07
P5V_SDA_PSW on TOP: 5.96,11.94 4.21,11.94 3.68,12.48 3.67,15.27 5.52,17.06 5.52,18.3 8.57,21.36 11.53,21.36 13.27,23.1 17.83,23.1 21.72,26.99 22.63,26.99 22.94,27.3 22.94,27.97 22.91,28 21.49,28 17.38,23.89 12.6,23.89 12.36,23.65 12.36,23.63 11.18,22.45 8.43,22.45 1.83,15.86 1.83,9.78 3.9,7.7 5.96,7.7
P5-9V_VIN on TOP: 11.38,1.96 11.38,9.88 11.84,10.34 11.84,10.92 11.85,10.93 11.85,11.26 11.65,11.46 10.04,11.46 9.76,11.18 9.76,4.83 9.09,4.16 8.39,4.16 8.32,4.09 8.32,1.74 8.48,1.59 11.01,1.59
P5-9V_VIN on BOTTOM: 8.77,3.81 8.77,6.16 9.17,6.56 9.17,10.7 10.8,12.32 27.71,12.32 30.01,10.03 30.01,7.85 29.71,7.55 27.17,7.55 26.74,7.12 26.74,7.12 26.74,1.71 27.14,1.31 43.67,1.31 45.29,2.92 45.29,2.96 45.97,2.96 46.71,2.23 46.71,0.95 46.07,0.31 26.28,0.31 25.65,0.94 25.65,7.77 26.28,8.4 26.28,10.82 25.9,11.19 12.2,11.19 11.08,10.07 11.08,10.07 10.65,9.63 10.68,9.6 10.68,3.87 10.39,3.58 9.78,3.58 9.76,3.6 8.98,3.6
P5-9V_VIN_VR on TOP: 6.09,14.98 5.73,14.62 5.73,12.95 6.43,12.25 6.43,10.61 6.57,10.47 9.15,10.47 9.15,11.09 9.67,11.61 24.64,11.61 25,11.25 30.46,11.25 30.95,11.73 30.95,13.87 30.64,14.18 23.09,14.18 21.61,12.71 11.87,12.71 11.04,13.54 11.04,14.69 10.74,14.98
SDA_USBSHIELD on TOP: 0.62,31.76 2.91,31.76 3.56,31.12 5.75,31.12 5.77,31.14 5.98,30.94 5.98,21.28 5.43,20.73 3.3,20.73 2.7,20.13 2.7,20.13 2.34,19.77 0.56,19.77 0.42,19.92 0.41,19.92 0.41,31.55 ; 3 cut-outs
SDA_USBSHIELD on BOTTOM: 0.66,32.61 4.87,32.61 6,31.48 6,21.27 4.51,19.78 0.72,19.78 0.5,20 0.5,32.45
V_TGTMCU on INT_1: 25.73,45.16 26.43,45.16 26.87,44.72 26.87,43.98 26.68,43.8 26.68,40.89 27.6,39.97 27.6,38.6 28.38,37.83 28.38,28.79 28.35,28.77 28.86,28.27 29.57,28.27 30.03,28.72 30.03,31.48 29.94,31.56 29.94,31.98 31.29,33.33 31.29,38.38 31.69,38.78 32.61,38.78 33.03,38.36 33.03,31.08 30.94,28.99 30.94,24.13 30.06,24.13 28.56,25.62 28.56,25.71 28.21,26.06 27.4,26.06 26.82,26.63 26.82,37.66 25.73,38.76

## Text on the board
BOTTOM: 7 OF 10 | SECONDARY SIDE
Board Geometry/Soldermask Bottom: 8 OF 10 | SECONDARY SOLDERMASK
Ref Des/Silkscreen Bottom: MCU | SW1 | RESET | 5V EXT GEN | SDA | GND | SDA RST | SCH | 700 | JACK | 5V PWR | SWD_DIO_TGTMCU | SWD_CLK_TGTMCU | P3V3_REG | P3V3_SDA | P3V3_K31 | B2 | B10 | NC | J2 | B0 | E24 | C6 | DP1 | ADC0 | J1 | _OUT | DAC0 | B19 | [PT] | C12 | C10 | E1 | E16 | OpenSDA | B20 | B1 | A17 | AREF | C7 | J3 | ADC1_SE23 | E17 | ADC1_SE18 | E19 | P3V3 | B18 | B3 | E18 | RST | D5 | ADC0_DP0 | D6 | D4 | A5 | ADC1_DP0 | C4 | 5V_USB | C5 | C2 | C1 | 5-9Vin | ADC0_DP1 | C8 | ADC0_DM1 | C9 | ADC0_DM0 | B11 | ADC1_DM0 | C0 | B21 | C11 | DAC0_OUT | J4 | E3 | C3 | E2 | A12 | C17 | C13 | C16 | E6 | C15 | E5 | A13 | E0 | 9 OF 10 | SECONDARY SILKSCREEN | FRDM-KV31F | Manufactured in PRC
User.Comments: 1 OF 1 | TEST PROBE | 1/1 | 1
TOP: 4 OF 10 | PRIMARY SIDE
Board Geometry/Soldermask Top: 3 OF 10 | PRIMARY SOLDERMASK
Ref Des/Silkscreen Top: SDA | USB | RESET | RST | GND | B | G | R | PWR 5V | 1 | JTAG | RGB | 2 OF 10 | PRIMARY SILKSCREEN | FRDM-KV31F
GND: 5 OF 10 | GROUND PLANE
INT_1: 6 OF 10 | INTERNAL 1
DIMENSION: GRID ORIGIN | PRIMARY DATUM
BODY_CENTER: 22. . | INTENTIONAL SHORT IN J19 BETWEEN P3V3 AND P3V3_REG | INTENTIONAL SHORT IN J20 BETWEEN P3V3 AND P3V3_KV31 | INTENTIONAL SHORT IN J8 BETWEEN SWD_CLK_TGTMCU_BUF AND OPENSDA | INTENTIONAL SHORT IN J5 BETWEEN NETS SDA_RST_TGTMCU_B AND SDA_RST_TGTMCU_J_B | INTENTIONAL SHORT IN SH1 BETWEEN NETS P3V3 AND V_TGTMCU | INTENTIONAL SHORT IN J11 BETWEEN SWD HEADER AND SWD_CLK_KV31AND SWD_CLK_TGTMCU | INTENTIONAL SHORT IN J12 SWD_DIO_TGTMCU_BUF AND OPENSDA | Core 40.567 mil | 1506 6.3535 mil | Theoretically Thickness 1.46mm
PASTEMASK_TOP: 1 OF 10 | PASTEMASK TOP
User.5: 10 OF 10 | SECONDARY PASTEMASK
User.14: . | B | C | D | E
User.17: Int_1 | TOP | layers | Trace spac | 5.2 | (mils) | 5.7 | Single ended | Impedance | 50 +/-5 | (Ohms) | Trace Width | 5 | 5.1 | Differential(USB all nets) | Trace spacing | 7.35 | 7.9 | 90 +/-10 | DETAIL B
User.20: FIGURE | SIZE | 10.0 | 18.0 | 28.0 | 40.0 | 50.0 | 63.0 | 125.0 | 34.0x30.0 | 59.0x33.0 | 91.0x32.0 | 111.0x32.0 | DRILL CHART: TOP to BOTTOM | ALL UNITS ARE IN MILS | TOLERANCE | +0.0/-10.0 | +2.0/-2.0 | +3.0/-3.0 | PLATED | NON-PLATED | QTY | 369 | 18 | 20 | 83 | 2 | 6 | 4 | 1
